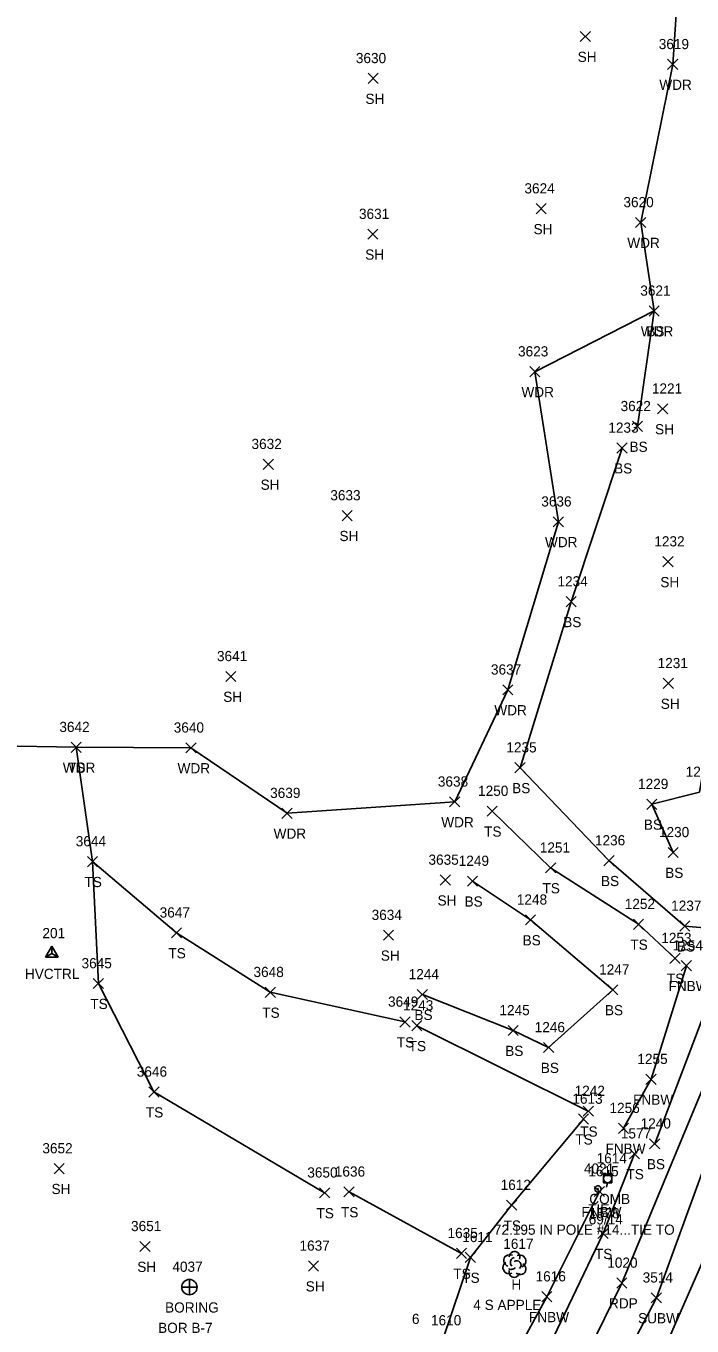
# Model space of a CAD drawing. Extents: x 1634209 to 1639641, y 608564 to 612258.
# Drawn here: x 1639192.5 to 1639323.4, y 611591.9 to 611847.1 of the extents above; entities that cross this region are included whole.
import ezdxf

# ---------------------------------------------------------------- set-up
doc = ezdxf.new("R2010")
doc.units = 0
for name, color, linetype in [('C_A', 7, 'Continuous'), ('C_C', 7, 'Continuous'), ('C_I', 7, 'Continuous'), ('CBP', 7, 'Continuous'), ('CPSM', 7, 'Continuous'), ('G_A', 7, 'Continuous'), ('G_C', 7, 'Continuous'), ('G_I', 7, 'Continuous'), ('GA_P', 7, 'Continuous'), ('L_A', 7, 'Continuous'), ('L_C', 7, 'Continuous'), ('L_I', 7, 'Continuous'), ('L_TIC', 7, 'Continuous'), ('LAWA', 7, 'Continuous'), ('LELB', 7, 'Continuous'), ('LFNC', 7, 'Continuous'), ('LTD', 7, 'Continuous'), ('P_A', 7, 'Continuous'), ('P_I', 7, 'Continuous'), ('P_TIC', 7, 'Continuous'), ('PET', 7, 'Continuous'), ('PRC', 7, 'Continuous'), ('U_A', 7, 'Continuous'), ('U_C', 7, 'Continuous'), ('U_I', 7, 'Continuous'), ('U_TIC', 7, 'Continuous'), ('UP', 7, 'Continuous'), ('UW', 7, 'Continuous')]:
    doc.layers.add(name, color=color, linetype=linetype)

msp = doc.modelspace()

# ---------------------------------------------------------------- linework, layer by layer
at = {"layer": 'CBP'}
for radius in [0.625, 0.0833]:
    msp.add_circle((1639304.92, 611618.8), radius, dxfattribs=at)
at = {"layer": 'CPSM'}
for p, q in [((1639196.38, 611664.3), (1639197.63, 611666.47)), ((1639198.88, 611664.3), (1639197.63, 611666.47)), ((1639197.63, 611665.02), (1639197.63, 611666.47)), ((1639196.38, 611664.3), (1639197.63, 611665.02)), ((1639196.38, 611664.3), (1639198.88, 611664.3)), ((1639197.63, 611665.02), (1639197.63, 611665.02)), ((1639197.63, 611665.02), (1639198.88, 611664.3))]:
    msp.add_line(p, q, dxfattribs=at)
at = {"layer": 'GA_P'}
for p, q in [((1639224.63, 611599.53), (1639223.13, 611599.53)), ((1639224.63, 611599.53), (1639224.63, 611601.03)), ((1639226.13, 611599.53), (1639224.63, 611599.53)), ((1639224.63, 611598.03), (1639224.63, 611599.53))]:
    msp.add_line(p, q, dxfattribs=at)
for start, end in [(90, 180), (180, 270), (0, 90), (270, 0)]:
    msp.add_arc((1639224.63, 611599.53), 1.5, start, end, dxfattribs=at)
at = {"layer": 'L_TIC'}
for points in [[(1639301.43, 611844.03), (1639303.43, 611846.03)], [(1639303.43, 611844.03), (1639301.43, 611846.03)], [(1639318.6, 611838.54), (1639320.6, 611840.54)], [(1639320.6, 611838.54), (1639318.6, 611840.54)], [(1639259.73, 611835.79), (1639261.73, 611837.79)], [(1639261.73, 611835.79), (1639259.73, 611837.79)], [(1639292.76, 611810.21), (1639294.76, 611812.21)], [(1639294.76, 611810.21), (1639292.76, 611812.21)], [(1639312.3, 611807.51), (1639314.3, 611809.51)], [(1639314.3, 611807.51), (1639312.3, 611809.51)], [(1639259.69, 611805.21), (1639261.69, 611807.21)], [(1639261.69, 611805.21), (1639259.69, 611807.21)], [(1639314.96, 611790.14), (1639316.96, 611792.14)], [(1639316.96, 611790.14), (1639314.96, 611792.14)], [(1639314.96, 611790.14), (1639316.96, 611792.14)], [(1639316.96, 611790.14), (1639314.96, 611792.14)], [(1639291.51, 611778.22), (1639293.51, 611780.22)], [(1639293.51, 611778.22), (1639291.51, 611780.22)], [(1639316.63, 611770.92), (1639318.63, 611772.92)], [(1639318.63, 611770.92), (1639316.63, 611772.92)], [(1639311.66, 611767.48), (1639313.66, 611769.48)], [(1639313.66, 611767.48), (1639311.66, 611769.48)], [(1639308.63, 611763.24), (1639310.63, 611765.24)], [(1639310.63, 611763.24), (1639308.63, 611765.24)], [(1639239.15, 611760.04), (1639241.15, 611762.04)], [(1639241.15, 611760.04), (1639239.15, 611762.04)], [(1639254.63, 611749.97), (1639256.63, 611751.97)], [(1639256.63, 611749.97), (1639254.63, 611751.97)], [(1639296.13, 611748.76), (1639298.13, 611750.76)], [(1639298.13, 611748.76), (1639296.13, 611750.76)], [(1639317.68, 611740.92), (1639319.68, 611742.92)], [(1639319.68, 611740.92), (1639317.68, 611742.92)], [(1639298.64, 611733.07), (1639300.64, 611735.07)], [(1639300.64, 611733.07), (1639298.64, 611735.07)], [(1639231.79, 611718.4), (1639233.79, 611720.4)], [(1639233.79, 611718.4), (1639231.79, 611720.4)], [(1639317.75, 611717.03), (1639319.75, 611719.03)], [(1639319.75, 611717.03), (1639317.75, 611719.03)], [(1639286.19, 611715.77), (1639288.19, 611717.77)], [(1639288.19, 611715.77), (1639286.19, 611717.77)], [(1639201.4, 611704.49), (1639203.4, 611706.49)], [(1639203.4, 611704.49), (1639201.4, 611706.49)], [(1639201.4, 611704.49), (1639203.4, 611706.49)], [(1639203.4, 611704.49), (1639201.4, 611706.49)], [(1639223.95, 611704.38), (1639225.95, 611706.38)], [(1639225.95, 611704.38), (1639223.95, 611706.38)], [(1639288.6, 611700.48), (1639290.6, 611702.48)], [(1639290.6, 611700.48), (1639288.6, 611702.48)], [(1639242.82, 611691.54), (1639244.82, 611693.54)], [(1639244.82, 611691.54), (1639242.82, 611693.54)], [(1639275.76, 611693.78), (1639277.76, 611695.78)], [(1639277.76, 611693.78), (1639275.76, 611695.78)], [(1639283.13, 611691.95), (1639285.13, 611693.95)], [(1639285.13, 611691.95), (1639283.13, 611693.95)], [(1639314.48, 611693.31), (1639316.48, 611695.31)], [(1639316.48, 611693.31), (1639314.48, 611695.31)], [(1639318.67, 611683.85), (1639320.67, 611685.85)], [(1639320.67, 611683.85), (1639318.67, 611685.85)], [(1639204.61, 611682.05), (1639206.61, 611684.05)], [(1639206.61, 611682.05), (1639204.61, 611684.05)], [(1639204.61, 611682.05), (1639206.61, 611684.05)], [(1639206.61, 611682.05), (1639204.61, 611684.05)], [(1639306.06, 611682.24), (1639308.06, 611684.24)], [(1639308.06, 611682.24), (1639306.06, 611684.24)], [(1639294.6, 611680.82), (1639296.6, 611682.82)], [(1639296.6, 611680.82), (1639294.6, 611682.82)], [(1639273.92, 611678.43), (1639275.92, 611680.43)], [(1639275.92, 611678.43), (1639273.92, 611680.43)], [(1639279.25, 611678.22), (1639281.25, 611680.22)], [(1639281.25, 611678.22), (1639279.25, 611680.22)], [(1639290.66, 611670.61), (1639292.66, 611672.61)], [(1639292.66, 611670.61), (1639290.66, 611672.61)], [(1639311.86, 611669.75), (1639313.86, 611671.75)], [(1639313.86, 611669.75), (1639311.86, 611671.75)], [(1639320.98, 611669.4), (1639322.98, 611671.4)], [(1639322.98, 611669.4), (1639320.98, 611671.4)], [(1639221.1, 611668.07), (1639223.1, 611670.07)], [(1639223.1, 611668.07), (1639221.1, 611670.07)], [(1639262.75, 611667.6), (1639264.75, 611669.6)], [(1639264.75, 611667.6), (1639262.75, 611669.6)], [(1639319.03, 611663.07), (1639321.03, 611665.07)], [(1639321.03, 611663.07), (1639319.03, 611665.07)], [(1639321.28, 611661.62), (1639323.28, 611663.62)], [(1639323.28, 611661.62), (1639321.28, 611663.62)], [(1639205.76, 611658.11), (1639207.76, 611660.11)], [(1639207.76, 611658.11), (1639205.76, 611660.11)], [(1639239.53, 611656.39), (1639241.53, 611658.39)], [(1639241.53, 611656.39), (1639239.53, 611658.39)], [(1639269.41, 611655.96), (1639271.41, 611657.96)], [(1639271.41, 611655.96), (1639269.41, 611657.96)], [(1639306.83, 611656.89), (1639308.83, 611658.89)], [(1639308.83, 611656.89), (1639306.83, 611658.89)], [(1639265.98, 611650.57), (1639267.98, 611652.57)], [(1639267.98, 611650.57), (1639265.98, 611652.57)], [(1639268.31, 611649.84), (1639270.31, 611651.84)], [(1639270.31, 611649.84), (1639268.31, 611651.84)], [(1639287.24, 611648.9), (1639289.24, 611650.9)], [(1639289.24, 611648.9), (1639287.24, 611650.9)], [(1639294.22, 611645.56), (1639296.22, 611647.56)], [(1639296.22, 611645.56), (1639294.22, 611647.56)], [(1639314.34, 611639.32), (1639316.34, 611641.32)], [(1639316.34, 611639.32), (1639314.34, 611641.32)], [(1639216.67, 611636.83), (1639218.67, 611638.83)], [(1639218.67, 611636.83), (1639216.67, 611638.83)], [(1639302.01, 611633.06), (1639304.01, 611635.06)], [(1639304.01, 611633.06), (1639302.01, 611635.06)], [(1639301.06, 611631.51), (1639303.06, 611633.51)], [(1639303.06, 611631.51), (1639301.06, 611633.51)], [(1639308.91, 611629.7), (1639310.91, 611631.7)], [(1639310.91, 611629.7), (1639308.91, 611631.7)], [(1639315.06, 611626.66), (1639317.06, 611628.66)], [(1639317.06, 611626.66), (1639315.06, 611628.66)], [(1639311.09, 611624.7), (1639313.09, 611626.7)], [(1639313.09, 611624.7), (1639311.09, 611626.7)], [(1639198.06, 611621.79), (1639200.06, 611623.79)], [(1639200.06, 611621.79), (1639198.06, 611623.79)], [(1639250.2, 611617.03), (1639252.2, 611619.03)], [(1639252.2, 611617.03), (1639250.2, 611619.03)], [(1639255.01, 611617.22), (1639257.01, 611619.22)], [(1639257.01, 611617.22), (1639255.01, 611619.22)], [(1639304.19, 611617.28), (1639306.19, 611619.28)], [(1639306.19, 611617.28), (1639304.19, 611619.28)], [(1639286.95, 611614.6), (1639288.95, 611616.6)], [(1639288.95, 611614.6), (1639286.95, 611616.6)], [(1639304.91, 611609.04), (1639306.91, 611611.04)], [(1639306.91, 611609.04), (1639304.91, 611611.04)], [(1639214.91, 611606.51), (1639216.91, 611608.51)], [(1639216.91, 611606.51), (1639214.91, 611608.51)], [(1639277.09, 611605.15), (1639279.09, 611607.15)], [(1639279.09, 611605.15), (1639277.09, 611607.15)], [(1639248.01, 611602.67), (1639250.01, 611604.67)], [(1639250.01, 611602.67), (1639248.01, 611604.67)], [(1639278.84, 611604.36), (1639280.84, 611606.36)], [(1639280.84, 611604.36), (1639278.84, 611606.36)], [(1639293.87, 611596.64), (1639295.87, 611598.64)], [(1639295.87, 611596.64), (1639293.87, 611598.64)]]:
    msp.add_lwpolyline(points, dxfattribs=at)
at = {"layer": 'LAWA'}
msp.add_lwpolyline([(1639360.4, 611945.78), (1639337.86, 611942.69), (1639328.3, 611925.99), (1639325.8, 611899.79), (1639322.13, 611876.77), (1639319.6, 611839.54), (1639313.3, 611808.51), (1639315.96, 611791.14), (1639292.51, 611779.22), (1639297.13, 611749.76), (1639287.19, 611716.77), (1639276.76, 611694.78), (1639243.82, 611692.54), (1639224.95, 611705.38), (1639202.4, 611705.49), (1639183.07, 611705.82), (1639163.18, 611694.66), (1639148.22, 611679.88), (1639133.72, 611654.57), (1639109.62, 611601.39), (1639094.77, 611617.67)], dxfattribs=at)
at = {"layer": 'LELB'}
for points in [[(1639390.61, 611912.03), (1639380.51, 611879.56), (1639366.54, 611835.06), (1639350.59, 611799.16), (1639345.37, 611765.77), (1639340.13, 611736.31), (1639333.62, 611715.99), (1639327.33, 611711.48), (1639324.83, 611696.7), (1639315.48, 611694.31), (1639319.67, 611684.85)], [(1639315.96, 611791.14), (1639312.66, 611768.48)], [(1639309.63, 611764.24), (1639299.64, 611734.07), (1639289.6, 611701.48), (1639307.06, 611683.24), (1639321.98, 611670.4), (1639326.57, 611669.97), (1639326.59, 611655.19), (1639316.06, 611627.66)], [(1639202.4, 611705.49), (1639205.61, 611683.05), (1639222.1, 611669.07), (1639240.53, 611657.39), (1639266.98, 611651.57)], [(1639284.13, 611692.95), (1639295.6, 611681.82), (1639312.86, 611670.75), (1639320.03, 611664.07)], [(1639205.61, 611683.05), (1639206.76, 611659.11), (1639217.67, 611637.83), (1639251.2, 611618.03)], [(1639270.41, 611656.96), (1639288.24, 611649.9), (1639295.22, 611646.56), (1639307.83, 611657.89), (1639291.66, 611671.61), (1639280.25, 611679.22)], [(1639303.01, 611634.06), (1639269.31, 611650.84)], [(1639255.89, 611534.05), (1639257.52, 611543.07), (1639257.09, 611554.85), (1639264.29, 611571.31), (1639274.36, 611589.02), (1639279.84, 611605.36), (1639287.95, 611615.6), (1639302.06, 611632.51)], [(1639312.09, 611625.7), (1639305.91, 611610.04), (1639294.63, 611586.44), (1639286.65, 611571.36), (1639276.42, 611548.75), (1639267.52, 611532.8), (1639255.94, 611511.09)], [(1639278.09, 611606.15), (1639256.01, 611618.22)]]:
    msp.add_lwpolyline(points, dxfattribs=at)
at = {"layer": 'LFNC'}
for points in [[(1639322.28, 611662.62), (1639315.34, 611640.32), (1639309.91, 611630.7)], [(1639305.19, 611618.28), (1639294.87, 611597.64), (1639288.56, 611586.13), (1639274.03, 611559.1), (1639258.54, 611531.07), (1639251.24, 611516.44), (1639241.97, 611495.12)]]:
    msp.add_lwpolyline(points, dxfattribs=at)
at = {"layer": 'LTD'}
msp.add_line((1639288.47, 611604.03), (1639288.47, 611604.03), dxfattribs=at)
msp.add_line((1639288.47, 611604.03), (1639288.47, 611604.03), dxfattribs=at)
msp.add_arc((1639288.52, 611605.47), 1.05, 335.5272, 180.9563, dxfattribs=at)
for centre, major_axis, ratio, start_param, end_param in [((1639287.39, 611603.33), (0.58, -1.04), 0.959034, 3.141593, 6.283185), ((1639287.68, 611604.7), (1.21, -0.51), 0.895232, 1.570796, 4.712389), ((1639288.26, 611604.49), (-0.208, -0.792), 0.645439, 3.141593, 6.283185), ((1639288.97, 611603.87), (-0.5, 0.667), 0.989748, 3.141593, 6.283185), ((1639289.47, 611603.2), (-1.09, 0.79), 0.841452, 1.570796, 4.712389), ((1639289.51, 611604.62), (-1.14, -0.48), 0.949671, 1.570796, 4.712389), ((1639288.47, 611602.53), (0.26, 1.06), 0.942809, 1.570796, 4.712389), ((1639288.01, 611603.28), (-0.625, -0.083), 0.423636, 0, 3.141593)]:
    msp.add_ellipse(centre, major_axis=major_axis, ratio=ratio, start_param=start_param, end_param=end_param, dxfattribs=at)
at = {"layer": 'P_TIC'}
for points in [[(1639308.59, 611599.33), (1639310.59, 611601.33)], [(1639310.59, 611599.33), (1639308.59, 611601.33)]]:
    msp.add_lwpolyline(points, dxfattribs=at)
at = {"layer": 'PET'}
msp.add_lwpolyline([(1639220.96, 611441.47), (1639247.22, 611483.75), (1639268.21, 611519.52), (1639285.57, 611551.38), (1639309.59, 611600.33), (1639328.5, 611645.78), (1639344.08, 611688.66), (1639358.64, 611735.43), (1639372.55, 611782.94), (1639389.96, 611841.92), (1639405.55, 611892.01), (1639422.64, 611939.83), (1639441.75, 611985.91), (1639461.99, 612028.31)], dxfattribs=at)
at = {"layer": 'PRC'}
msp.add_lwpolyline([(1639473.49, 612022.53), (1639453.52, 611981.45), (1639432.7, 611930.67), (1639416.88, 611885.46), (1639401.13, 611834.82), (1639385.48, 611780.16), (1639369.66, 611726.72), (1639353.84, 611677.52), (1639335.57, 611627.61), (1639314.72, 611580.03), (1639292.65, 611536.14), (1639275.3, 611504.78), (1639250.46, 611462.84), (1639222.36, 611418.18)], dxfattribs=at)
at = {"layer": 'U_TIC'}
for points in [[(1639315.38, 611596.42), (1639317.38, 611598.42)], [(1639317.38, 611596.42), (1639315.38, 611598.42)]]:
    msp.add_lwpolyline(points, dxfattribs=at)
at = {"layer": 'UP'}
for p, q in [((1639307.06, 611622.5), (1639306.81, 611621.67)), ((1639305.98, 611620), (1639305.98, 611621.67)), ((1639305.98, 611621.67), (1639307.64, 611621.67)), ((1639307.64, 611620), (1639305.98, 611620)), ((1639306.56, 611619.17), (1639306.81, 611620)), ((1639306.81, 611620.83), (1639306.81, 611620.83)), ((1639307.64, 611621.67), (1639307.64, 611620))]:
    msp.add_line(p, q, dxfattribs=at)
msp.add_circle((1639306.81, 611620.83), 0.833, dxfattribs=at)
at = {"layer": 'UW'}
msp.add_lwpolyline([(1639594.99, 612226.51), (1639569.63, 612190.35), (1639550.67, 612164.48), (1639527.14, 612128.9), (1639506.92, 612097.5), (1639485.03, 612062.24), (1639463.29, 612024.05), (1639448.18, 611991.92), (1639428.21, 611945.59), (1639409.39, 611896.28), (1639395.47, 611852.57), (1639388.14, 611826.68), (1639366.36, 611747.21), (1639350.92, 611692.02), (1639316.38, 611597.42), (1639292.15, 611550.99), (1639279.15, 611528.72), (1639253.95, 611487.01), (1639229.78, 611449.06), (1639200.46, 611402.5), (1639172.27, 611358.67), (1639148.82, 611320.98)], dxfattribs=at)

# ---------------------------------------------------------------- texts
at = {"layer": 'C_A'}
for s, p in [('HVCTRL', (1639192.32, 611660.02)), ('TIE', (1639303, 611613.8))]:
    msp.add_text(s, height=2, dxfattribs=at).set_placement(p)
at = {"layer": 'C_C'}
msp.add_text('72.195 IN POLE #14...TIE TO', height=2, dxfattribs=at).set_placement((1639284.46, 611609.8))
at = {"layer": 'C_I'}
for s, p in [('201', (1639195.76, 611668.02)), ('4021', (1639302.15, 611621.8)), ('6', (1639268.36, 611592.29))]:
    msp.add_text(s, height=2, dxfattribs=at).set_placement(p)
at = {"layer": 'G_A'}
msp.add_text('BORING', height=2, dxfattribs=at).set_placement((1639219.86, 611594.53))
at = {"layer": 'G_C'}
msp.add_text('BOR B-7', height=2, dxfattribs=at).set_placement((1639218.49, 611590.53))
at = {"layer": 'G_I'}
msp.add_text('4037', height=2, dxfattribs=at).set_placement((1639221.29, 611602.53))
at = {"layer": 'L_A'}
for s, p in [('SH', (1639300.92, 611840.03)), ('WDR', (1639316.96, 611834.54)), ('SH', (1639259.22, 611831.79)), ('SH', (1639292.25, 611806.21)), ('SH', (1639259.18, 611801.21)), ('WDR', (1639310.67, 611803.51)), ('WDR', (1639313.32, 611786.14)), ('BS', (1639314.4, 611786.14)), ('WDR', (1639289.87, 611774.22)), ('SH', (1639316.12, 611766.92)), ('BS', (1639311.1, 611763.48)), ('BS', (1639308.07, 611759.24)), ('SH', (1639238.63, 611756.04)), ('SH', (1639254.12, 611745.97)), ('WDR', (1639294.5, 611744.76)), ('SH', (1639317.16, 611736.92)), ('BS', (1639298.08, 611729.07)), ('SH', (1639231.28, 611714.4)), ('SH', (1639317.24, 611713.03)), ('WDR', (1639284.55, 611711.77)), ('WDR', (1639199.76, 611700.49)), ('TS', (1639200.81, 611700.49)), ('WDR', (1639222.31, 611700.38)), ('BS', (1639288.04, 611696.48)), ('WDR', (1639274.12, 611689.78)), ('BS', (1639313.92, 611689.31)), ('WDR', (1639241.18, 611687.54)), ('TS', (1639282.54, 611687.95)), ('BS', (1639318.11, 611679.85)), ('TS', (1639204.02, 611678.05)), ('TS', (1639204.02, 611678.05)), ('TS', (1639294.01, 611676.82)), ('BS', (1639305.5, 611678.24)), ('SH', (1639273.4, 611674.43)), ('BS', (1639278.69, 611674.22)), ('BS', (1639290.1, 611666.61)), ('TS', (1639220.51, 611664.07)), ('SH', (1639262.24, 611663.6)), ('TS', (1639311.27, 611665.75)), ('BS', (1639320.42, 611665.4)), ('TS', (1639318.44, 611659.07)), ('FNBW', (1639318.76, 611657.62)), ('TS', (1639205.17, 611654.11)), ('TS', (1639238.94, 611652.39)), ('BS', (1639268.85, 611651.96)), ('BS', (1639306.27, 611652.89)), ('TS', (1639265.38, 611646.57)), ('TS', (1639267.72, 611645.84)), ('BS', (1639286.68, 611644.9)), ('BS', (1639293.67, 611641.56)), ('FNBW', (1639311.81, 611635.32)), ('TS', (1639216.08, 611632.83)), ('TS', (1639301.42, 611629.06)), ('TS', (1639300.47, 611627.51)), ('FNBW', (1639306.39, 611625.7)), ('BS', (1639314.51, 611622.66)), ('TS', (1639310.5, 611620.7)), ('SH', (1639197.55, 611617.79)), ('TS', (1639249.61, 611613.03)), ('TS', (1639254.42, 611613.22)), ('FNBW', (1639301.66, 611613.28)), ('TS', (1639286.36, 611610.6)), ('TS', (1639304.32, 611605.04)), ('SH', (1639214.4, 611602.51)), ('TS', (1639276.5, 611601.15)), ('TS', (1639278.25, 611600.36)), ('SH', (1639247.49, 611598.67)), ('H', (1639287.9, 611599.03)), ('FNBW', (1639291.35, 611592.64))]:
    msp.add_text(s, height=2, dxfattribs=at).set_placement(p)
at = {"layer": 'L_C'}
msp.add_text('4 S APPLE', height=2, dxfattribs=at).set_placement((1639280.41, 611595.03))
at = {"layer": 'L_I'}
for s, p in [('3619', (1639316.85, 611842.54)), ('3630', (1639257.34, 611839.79)), ('3624', (1639290.46, 611814.21)), ('3620', (1639309.91, 611811.51)), ('3631', (1639257.95, 611809.21)), ('3621', (1639313.22, 611794.14)), ('3621', (1639313.22, 611794.14)), ('3623', (1639289.2, 611782.22)), ('1221', (1639315.5, 611774.92)), ('3622', (1639309.35, 611771.48)), ('1233', (1639306.94, 611767.24)), ('3632', (1639236.84, 611764.04)), ('3633', (1639252.32, 611753.97)), ('3636', (1639293.77, 611752.76)), ('1232', (1639315.98, 611744.92)), ('1234', (1639296.95, 611737.07)), ('3641', (1639230.05, 611722.4)), ('3637', (1639283.88, 611719.77)), ('1231', (1639316.62, 611721.03)), ('3642', (1639199.09, 611708.49)), ('3642', (1639199.09, 611708.49)), ('3640', (1639221.56, 611708.38)), ('1235', (1639286.91, 611704.48)), ('1228', (1639322.14, 611699.7)), ('3638', (1639273.45, 611697.78)), ('1229', (1639312.78, 611697.31)), ('3639', (1639240.5, 611695.54)), ('1250', (1639281.35, 611695.95)), ('1230', (1639316.89, 611687.85)), ('3644', (1639202.31, 611686.05)), ('3644', (1639202.31, 611686.05)), ('1251', (1639293.48, 611684.82)), ('1236', (1639304.31, 611686.24)), ('3635', (1639271.61, 611682.43)), ('1249', (1639277.55, 611682.22)), ('1248', (1639288.97, 611674.61)), ('1252', (1639310.17, 611673.75)), ('3647', (1639218.79, 611672.07)), ('3634', (1639260.44, 611671.6)), ('1237', (1639319.29, 611673.4)), ('1253', (1639317.34, 611667.07)), ('1254', (1639319.59, 611665.62)), ('3645', (1639203.45, 611662.11)), ('1247', (1639305.14, 611660.89)), ('3648', (1639237.23, 611660.39)), ('1244', (1639267.72, 611659.96)), ('3649', (1639263.66, 611654.57)), ('1243', (1639266.61, 611653.84)), ('1245', (1639285.55, 611652.9)), ('1246', (1639292.48, 611649.56)), ('1255', (1639312.65, 611643.32)), ('3646', (1639214.3, 611640.83)), ('1613', (1639299.88, 611635.51)), ('1242', (1639300.32, 611637.06)), ('1256', (1639307.17, 611633.7)), ('1240', (1639313.29, 611630.66)), ('1577', (1639309.4, 611628.7)), ('3652', (1639195.75, 611625.79)), ('3650', (1639247.8, 611621.03)), ('1636', (1639253.21, 611621.22)), ('1615', (1639303.02, 611621.28)), ('1612', (1639285.78, 611618.6)), ('1578', (1639303.22, 611613.04)), ('3651', (1639213.17, 611610.51)), ('1635', (1639275.35, 611609.15)), ('1611', (1639278.24, 611608.36)), ('1637', (1639246.27, 611606.67)), ('1617', (1639286.3, 611607.03)), ('1616', (1639292.65, 611600.64)), ('1610', (1639272.1, 611592.02))]:
    msp.add_text(s, height=2, dxfattribs=at).set_placement(p)
at = {"layer": 'P_A'}
msp.add_text('RDP', height=2, dxfattribs=at).set_placement((1639307.08, 611595.33))
at = {"layer": 'P_I'}
msp.add_text('1020', height=2, dxfattribs=at).set_placement((1639306.73, 611603.33))
at = {"layer": 'U_A'}
for s, p in [('COMB', (1639303.2, 611615.83)), ('SUBW', (1639312.79, 611592.42))]:
    msp.add_text(s, height=2, dxfattribs=at).set_placement(p)
at = {"layer": 'U_C'}
msp.add_text('69/14', height=2, dxfattribs=at).set_placement((1639303.09, 611611.83))
at = {"layer": 'U_I'}
for s, p in [('1614', (1639304.64, 611623.83)), ('3514', (1639313.69, 611600.42))]:
    msp.add_text(s, height=2, dxfattribs=at).set_placement(p)

doc.saveas('drawing.dxf')
